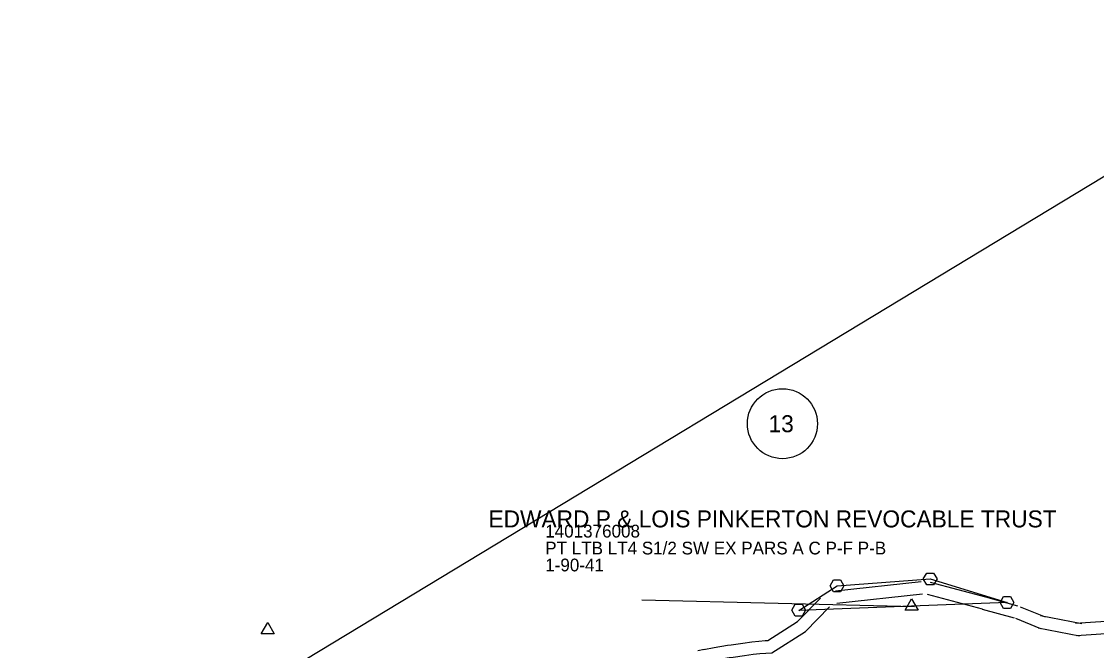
# Model space of a CAD drawing. Extents: x 14265071 to 14303042, y 8620873 to 8637932.
# Drawn here: x 14284549.1 to 14284979.3, y 8637680.6 to 8637932.4 of the extents above; entities that cross this region are included whole.
import ezdxf

# ---------------------------------------------------------------- set-up
doc = ezdxf.new("R2010")
doc.units = 0
for name, color, linetype in [('_CIVIL_CONSTRUCTION', 7, 'Continuous'), ('Alignment', 7, 'Continuous'), ('Profile', 7, 'Continuous'), ('TextAlignment', 7, 'Continuous'), ('TextAlignmentLrg', 7, 'Continuous'), ('TextAlignmentSml', 7, 'Continuous')]:
    doc.layers.add(name, color=color, linetype=linetype)

msp = doc.modelspace()

# ---------------------------------------------------------------- linework, layer by layer
at = {"layer": '_CIVIL_CONSTRUCTION'}
for p, q in [((14284874.91, 8637704.51), (14284909.13, 8637708.25)), ((14284912.8, 8637707.97), (14284934.86, 8637702.08)), ((14284875.45, 8637699.54), (14284909.68, 8637703.28)), ((14284911.51, 8637703.14), (14284933.57, 8637697.25)), ((14284934.96, 8637702.05), (14284947.66, 8637698.52)), ((14284797.39, 8637700.92), (14284906.54, 8637698.27)), ((14284933.62, 8637697.23), (14284946.32, 8637693.7)), ((14284948.72, 8637698.16), (14284958.78, 8637694.1)), ((14284946.85, 8637693.52), (14284956.91, 8637689.47)), ((14284956.95, 8637694.64), (14284973.45, 8637691.43)), ((14284970.86, 8637691.59), (14284999.5, 8637693.54)), ((14284956, 8637689.74), (14284972.49, 8637686.52)), ((14284971.2, 8637686.6), (14284999.84, 8637688.55)), ((14284819.76, 8637680.65), (14284822.36, 8637681.1))]:
    msp.add_line(p, q, dxfattribs=at)
for points in [[(14284822.25, 8637681.08), (14284826.31, 8637681.83), (14284831.61, 8637682.7), (14284833.18, 8637682.93), (14284837.81, 8637683.6), (14284841.37, 8637684.09), (14284844.14, 8637684.38), (14284846.74, 8637684.59), (14284847.85, 8637684.64), (14284859.7, 8637692.18), (14284868.84, 8637701.55)], [(14284823.16, 8637676.16), (14284827.18, 8637676.91), (14284832.36, 8637677.76), (14284833.89, 8637677.98), (14284838.51, 8637678.65), (14284841.98, 8637679.13), (14284844.61, 8637679.4), (14284847.04, 8637679.6), (14284849.4, 8637679.7), (14284862.87, 8637688.27), (14284872.42, 8637698.06)]]:
    msp.add_lwpolyline(points, dxfattribs=at)
at = {"layer": 'Alignment'}
msp.add_circle((14284853.64, 8637771.42), 14.01, dxfattribs=at)
at = {"layer": 'Profile'}
for p, q in [((14284860.14, 8637696.66), (14284875.5, 8637706.49)), ((14284875.5, 8637706.49), (14284912.76, 8637709.26)), ((14284912.76, 8637709.26), (14284943.51, 8637699.86))]:
    msp.add_line(p, q, dxfattribs=at)
at = {"layer": 'TextAlignment'}
msp.add_lwpolyline([(14284549.13, 8637608.21), (14284756.21, 8637265.98), (14285292.07, 8637590.22), (14285084.99, 8637932.44)], close=True, dxfattribs=at)
at = {"layer": 'TextAlignmentLrg'}
for p, q in [((14284860.14, 8637696.66), (14284875.5, 8637706.49)), ((14284875.5, 8637706.49), (14284912.76, 8637709.26)), ((14284912.76, 8637709.26), (14284943.51, 8637699.86)), ((14284905.32, 8637698.33), (14284860.14, 8637696.66)), ((14284943.51, 8637699.86), (14284905.32, 8637698.33))]:
    msp.add_line(p, q, dxfattribs=at)
at = {"layer": 'TextAlignmentSml'}
for p, q in [((14284910.01, 8637709.26), (14284911.39, 8637711.64)), ((14284911.39, 8637711.64), (14284914.14, 8637711.64)), ((14284914.14, 8637711.64), (14284915.51, 8637709.26)), ((14284872.75, 8637706.49), (14284874.12, 8637708.87)), ((14284874.12, 8637704.1), (14284872.75, 8637706.49)), ((14284874.12, 8637708.87), (14284876.87, 8637708.87)), ((14284876.87, 8637708.87), (14284878.25, 8637706.49)), ((14284878.25, 8637706.49), (14284876.87, 8637704.1)), ((14284911.39, 8637706.88), (14284910.01, 8637709.26)), ((14284914.14, 8637706.88), (14284911.39, 8637706.88)), ((14284915.51, 8637709.26), (14284914.14, 8637706.88)), ((14284876.87, 8637704.1), (14284874.12, 8637704.1)), ((14284940.76, 8637699.86), (14284942.14, 8637702.24)), ((14284942.14, 8637702.24), (14284944.89, 8637702.24)), ((14284944.89, 8637702.24), (14284946.26, 8637699.86)), ((14284857.41, 8637696.77), (14284858.78, 8637699.15)), ((14284858.78, 8637699.15), (14284861.53, 8637699.15)), ((14284861.53, 8637699.15), (14284862.91, 8637696.77)), ((14284902.69, 8637696.78), (14284905.31, 8637701.32)), ((14284905.31, 8637701.32), (14284907.94, 8637696.78)), ((14284942.14, 8637697.48), (14284940.76, 8637699.86)), ((14284944.89, 8637697.48), (14284942.14, 8637697.48)), ((14284946.26, 8637699.86), (14284944.89, 8637697.48)), ((14284858.78, 8637694.39), (14284857.41, 8637696.77)), ((14284861.53, 8637694.39), (14284858.78, 8637694.39)), ((14284862.91, 8637696.77), (14284861.53, 8637694.39)), ((14284907.94, 8637696.78), (14284902.69, 8637696.78)), ((14284645.06, 8637687.29), (14284647.69, 8637691.84)), ((14284647.69, 8637691.84), (14284650.31, 8637687.29)), ((14284650.31, 8637687.29), (14284645.06, 8637687.29))]:
    msp.add_line(p, q, dxfattribs=at)

# ---------------------------------------------------------------- texts
at = {"layer": '_CIVIL_CONSTRUCTION'}
for s, p in [('1401376008', (14284758.71, 8637725.86)), ('PT LTB LT4 S1/2 SW EX PARS A C P-F P-B', (14284758.71, 8637719.08)), ('1-90-41', (14284758.71, 8637712.3))]:
    msp.add_text(s, height=5.1, dxfattribs=at).set_placement(p)
at = {"layer": 'Alignment'}
for s, p in [('13', (14284848.08, 8637768.02)), ('EDWARD P & LOIS PINKERTON REVOCABLE TRUST', (14284736, 8637729.9))]:
    msp.add_text(s, height=6.8, dxfattribs=at).set_placement(p)

doc.saveas('drawing.dxf')
